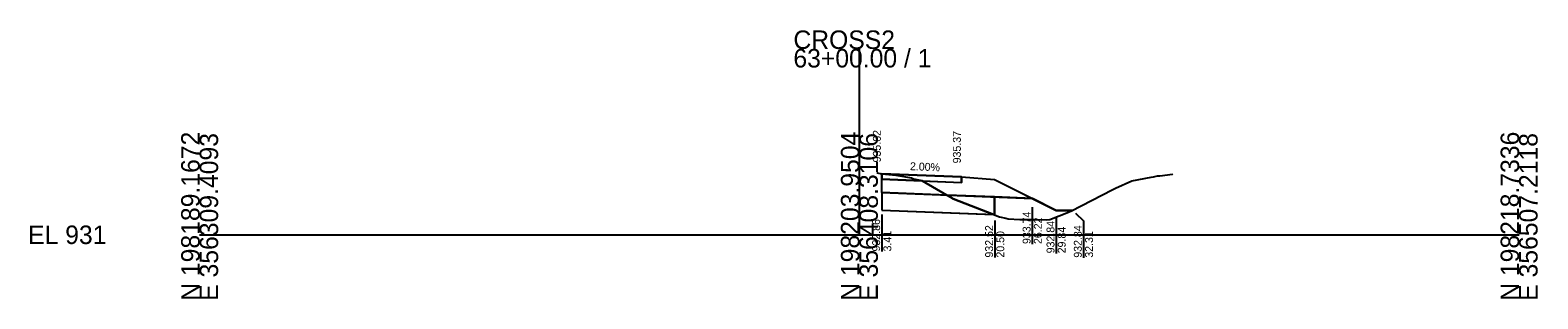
# Model space of a CAD drawing. Extents: x -26 to 203, y -10 to 14021.
# Drawn here: x -25.7 to 202.8, y 3990.3 to 4031 of the extents above; entities that cross this region are included whole.
import ezdxf

# ---------------------------------------------------------------- set-up
doc = ezdxf.new("R2010")
doc.units = 0
for name, color, linetype in [('Default', 7, 'Continuous'), ('P_E_XS_Ground', 7, 'Continuous'), ('P_XS', 7, 'Continuous'), ('P_XS_EAR_CommonGrnd', 7, 'Continuous'), ('P_XS_Lane', 7, 'Continuous'), ('P_XS_Rock', 7, 'Continuous')]:
    doc.layers.add(name, color=color, linetype=linetype)

msp = doc.modelspace()

# ---------------------------------------------------------------- linework, layer by layer
at = {"layer": 'Default'}
for p, q in [((100, 4000), (100, 4028.13)), ((0, 4000), (100, 4000)), ((100, 4000), (200, 4000))]:
    msp.add_line(p, q, dxfattribs=at)
at = {"layer": 'P_E_XS_Ground'}
for p, q in [((102.66, 4009.38), (103.13, 4009.26)), ((103.13, 4009.26), (105.55, 4009)), ((105.55, 4009), (107.88, 4008.61)), ((107.88, 4008.61), (108.18, 4008.49)), ((108.18, 4008.49), (109.46, 4008.2)), ((141.28, 4008.15), (144.21, 4008.72)), ((144.21, 4008.72), (144.59, 4008.79)), ((144.59, 4008.79), (145.18, 4008.92)), ((145.18, 4008.92), (145.52, 4008.92)), ((145.52, 4008.92), (147.47, 4009.2)), ((147.47, 4009.2), (147.5, 4009.23)), ((109.46, 4008.2), (113.79, 4005.69)), ((132.15, 4003.6), (138.31, 4006.79)), ((138.31, 4006.79), (138.84, 4007.04)), ((138.84, 4007.04), (141.28, 4008.15)), ((113.79, 4005.69), (114.21, 4005.46)), ((114.21, 4005.46), (121.24, 4002.7)), ((121.24, 4002.7), (122.2, 4002.54)), ((122.2, 4002.54), (122.56, 4002.41)), ((122.56, 4002.41), (124.3, 4002.29)), ((124.3, 4002.29), (124.9, 4002.29)), ((124.9, 4002.29), (126.46, 4002.33)), ((126.46, 4002.33), (128.42, 4002.24)), ((128.42, 4002.24), (128.85, 4002.31)), ((128.85, 4002.31), (131.68, 4003.4)), ((131.68, 4003.4), (132.15, 4003.6))]:
    msp.add_line(p, q, dxfattribs=at)
at = {"layer": 'P_XS'}
for p, q in [((103.41, 4009.23), (103.41, 4008.4)), ((115.5, 4008.75), (115.5, 4007.91)), ((103.41, 4008.4), (115.5, 4007.91)), ((103.41, 4006.4), (103.41, 4008.4)), ((103.41, 4006.4), (126.22, 4005.49)), ((103.41, 4006.4), (103.41, 4003.73)), ((120.5, 4005.72), (120.5, 4003.05)), ((103.41, 4003.73), (120.5, 4003.05))]:
    msp.add_line(p, q, dxfattribs=at)
at = {"layer": 'P_XS_EAR_CommonGrnd'}
for points in [[(108.18, 4008.49), (109.46, 4008.2), (109.53, 4008.15), (115.5, 4007.91), (115.5, 4008.75), (103.41, 4009.23), (105.55, 4009), (107.88, 4008.61)], [(108.18, 4008.49), (109.46, 4008.2), (109.53, 4008.15), (103.41, 4008.4), (103.41, 4009.23), (105.55, 4009), (107.88, 4008.61)], [(120.5, 4008.35), (126.22, 4005.49), (120.5, 4005.72), (113.25, 4006), (109.53, 4008.15), (115.5, 4007.91), (115.5, 4008.75)], [(103.41, 4006.4), (103.41, 4008.4), (109.53, 4008.15), (113.25, 4006)], [(103.41, 4003.73), (120.34, 4003.05), (114.21, 4005.46), (113.79, 4005.69), (113.25, 4006), (103.41, 4006.4)], [(113.79, 4005.69), (114.21, 4005.46), (120.34, 4003.05), (120.5, 4003.05), (120.5, 4005.72), (113.25, 4006)], [(124.9, 4002.29), (126.46, 4002.33), (128.42, 4002.24), (128.85, 4002.31), (131.68, 4003.4), (132.15, 4003.6), (132.31, 4003.68), (129.84, 4003.68), (126.22, 4005.49), (120.5, 4005.72), (120.5, 4003.05), (120.34, 4003.05), (121.24, 4002.7), (122.2, 4002.54), (122.56, 4002.41), (124.3, 4002.29)]]:
    msp.add_lwpolyline(points, close=True, dxfattribs=at)
at = {"layer": 'P_XS_Lane'}
for p, q in [((103.41, 4009.23), (115.5, 4008.75)), ((115.5, 4008.75), (120.5, 4008.35)), ((120.5, 4008.35), (129.84, 4003.68)), ((129.84, 4003.68), (132.31, 4003.68))]:
    msp.add_line(p, q, dxfattribs=at)
at = {"layer": 'P_XS_Rock'}
for p, q in [((126.2, 4004.19), (126.2, 3998.6)), ((103.39, 4003.06), (103.39, 3997.47)), ((120.51, 4002.15), (120.51, 3996.55)), ((129.82, 4002.79), (129.82, 3997.19)), ((132.76, 4003.25), (133.96, 4002.12)), ((133.96, 4002.12), (133.96, 3996.53))]:
    msp.add_line(p, q, dxfattribs=at)

# ---------------------------------------------------------------- texts
at = {"layer": 'Default'}
for s, p in [('CROSS2', (90, 4028.13)), ('63+00.00 / 1', (90, 4025.33)), ('EL 931', (-26, 3998.6))]:
    msp.add_text(s, height=2.8, dxfattribs=at).set_placement(p)
for s, p in [('N 198189.1672', (0, 3990)), ('N 198203.9504', (100, 3990)), ('N 198218.7336', (200, 3990)), ('E 356309.4093', (2.8, 3990)), ('E 356408.3106', (102.8, 3990)), ('E 356507.2118', (202.8, 3990))]:
    msp.add_text(s, height=2.8, rotation=90, dxfattribs=at).set_placement(p)
at = {"layer": 'P_XS_Rock'}
for s, rotation, p in [('935.62', 90, (103.25, 4010.95)), ('935.37', 90, (115.38, 4010.81)), ('2.00%', 357.7094, (107.65, 4009.79)), ('932.86', 90, (103.14, 3997.47)), ('933.74', 90, (125.95, 3998.6)), ('26.22', 90, (127.65, 3998.6)), ('932.84', 90, (129.57, 3997.19)), ('3.41', 90, (104.84, 3997.47)), ('932.52', 90, (120.26, 3996.55)), ('20.50', 90, (121.96, 3996.55)), ('29.84', 90, (131.27, 3997.19)), ('932.84', 90, (133.71, 3996.53)), ('32.31', 90, (135.41, 3996.53))]:
    msp.add_text(s, height=1.2, rotation=rotation, dxfattribs=at).set_placement(p)

doc.saveas('drawing.dxf')
